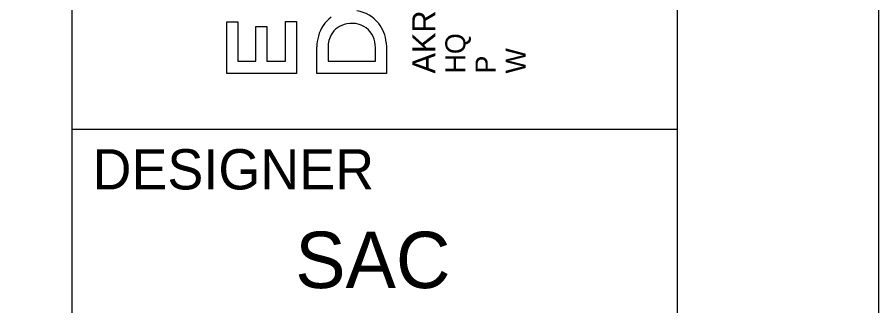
# Model space of a CAD drawing. Extents: x -0.2 to 34, y 0 to 22.
# Drawn here: x 31.863 to 34, y 2.061 to 2.778 of the extents above; entities that cross this region are included whole.
import ezdxf

# ---------------------------------------------------------------- set-up
doc = ezdxf.new("R2010")
doc.units = 0
for name, color, linetype in [('SG_P_Poles', 7, 'Continuous'), ('SH_Data', 7, 'Continuous'), ('SH_Masking', 7, 'Continuous')]:
    doc.layers.add(name, color=color, linetype=linetype)

msp = doc.modelspace()

# ---------------------------------------------------------------- linework, layer by layer
at = {"layer": 'SG_P_Poles'}
for p, q in [((32, 0.5), (32, 21.5)), ((32, 2.5), (33.5, 2.5))]:
    msp.add_line(p, q, dxfattribs=at)
msp.add_lwpolyline([(1.5, 21.5), (33.5, 21.5), (33.5, 0.5), (1.5, 0.5)], close=True, dxfattribs=at)
at = {"layer": 'SH_Data'}
for p, q in [((32.383, 2.6379), (32.383, 2.766)), ((32.383, 2.766), (32.4101, 2.766)), ((32.4101, 2.766), (32.4101, 2.6683)), ((32.5286, 2.6683), (32.5286, 2.7672)), ((32.5286, 2.7672), (32.5557, 2.7672)), ((32.5557, 2.7672), (32.5557, 2.6379)), ((32.455, 2.6683), (32.455, 2.7549)), ((32.455, 2.7549), (32.4822, 2.7549)), ((32.4822, 2.7549), (32.4822, 2.6683)), ((32.7785, 2.715), (32.7792, 2.7021)), ((32.6064, 2.638), (32.6064, 2.704)), ((32.6347, 2.7118), (32.6341, 2.7023)), ((32.6341, 2.7023), (32.6341, 2.6684)), ((32.7515, 2.6683), (32.7515, 2.7024)), ((32.7792, 2.7021), (32.7792, 2.638)), ((32.4101, 2.6683), (32.455, 2.6683)), ((32.4822, 2.6683), (32.5286, 2.6683)), ((32.6341, 2.6684), (32.7515, 2.6683)), ((32.5557, 2.6379), (32.383, 2.6379)), ((32.7792, 2.638), (32.6064, 2.638))]:
    msp.add_line(p, q, dxfattribs=at)
msp.add_lwpolyline([(32.383, 2.6379), (32.383, 2.766), (32.4101, 2.766), (32.4101, 2.6683), (32.455, 2.6683), (32.455, 2.7549), (32.4822, 2.7549), (32.4822, 2.6683), (32.5286, 2.6683), (32.5286, 2.7672), (32.5557, 2.7672), (32.5557, 2.6379)], close=True, dxfattribs=at)
for points in [[(32.7785, 2.715), (32.7792, 2.7021), (32.7792, 2.638), (32.6064, 2.638)], [(32.6064, 2.638), (32.6064, 2.704)], [(32.6347, 2.7118), (32.6341, 2.7023), (32.6341, 2.6684), (32.7515, 2.6683), (32.7515, 2.7024)]]:
    msp.add_lwpolyline(points, dxfattribs=at)
for centre, radius, start, end in [((32.6939, 2.7089), 0.0865, 127.2362, 165.148), ((32.6939, 2.7089), 0.0865, 127.2362, 165.148), ((32.6946, 2.7113), 0.0827, 37.8521, 82.402), ((32.6946, 2.7113), 0.0827, 37.8521, 82.402), ((32.6889, 2.7078), 0.054, 106.1881, 157.3861), ((32.6889, 2.7078), 0.054, 106.1881, 157.3861), ((32.6928, 2.6986), 0.0639, 55.6727, 107.2093), ((32.6928, 2.6986), 0.0639, 55.6727, 107.2093), ((32.6859, 2.7057), 0.0931, 5.7333, 37.304), ((32.6859, 2.7057), 0.0931, 5.7333, 37.304), ((32.6929, 2.705), 0.0587, 357.4662, 52.2665), ((32.6929, 2.705), 0.0587, 357.4662, 52.2665), ((32.7143, 2.7028), 0.1078, 164.7861, 179.3704), ((32.7143, 2.7028), 0.1078, 164.7861, 179.3704), ((32.6983, 2.7039), 0.0641, 157.3571, 172.9275), ((32.6983, 2.7039), 0.0641, 157.3571, 172.9275)]:
    msp.add_arc(centre, radius, start, end, dxfattribs=at)
at = {"layer": 'SH_Masking'}
msp.add_lwpolyline([(0, 0), (34, 0), (34, 22), (0, 22)], close=True, dxfattribs=at)

# ---------------------------------------------------------------- texts
at = {"layer": 'SH_Data'}
for s, height, p in [('AKRON / CLEVELAND / COLUMBUS', 0.056969, (32.9001, 2.638)), ('HQ ', 0.04985, (32.9749, 2.638)), ('W', 0.0498, (33.1244, 2.638)), ('P', 0.0498, (33.0497, 2.638))]:
    msp.add_text(s, height=height, rotation=90, dxfattribs=at).set_placement(p)
for s, height, p in [('DESIGNER', 0.1, (32.05, 2.35)), ('SAC', 0.14, (32.5528, 2.105))]:
    msp.add_text(s, height=height, dxfattribs=at).set_placement(p)

doc.saveas('drawing.dxf')
